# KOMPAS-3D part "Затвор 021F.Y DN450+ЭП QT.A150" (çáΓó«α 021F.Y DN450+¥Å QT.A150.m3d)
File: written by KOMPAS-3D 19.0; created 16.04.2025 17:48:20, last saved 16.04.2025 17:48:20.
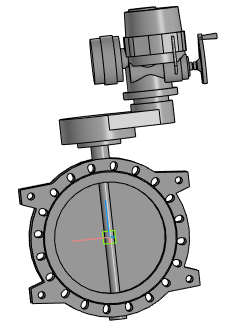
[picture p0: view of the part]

Document properties: Полное имя файла: Затвор 021F.Y DN450+ЭП QT.A150.a3d

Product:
- Part/product: Затвор 021F.Y DN450+ЭП QT.A150
    Масса: 364.874

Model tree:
1. Операция без истории:1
